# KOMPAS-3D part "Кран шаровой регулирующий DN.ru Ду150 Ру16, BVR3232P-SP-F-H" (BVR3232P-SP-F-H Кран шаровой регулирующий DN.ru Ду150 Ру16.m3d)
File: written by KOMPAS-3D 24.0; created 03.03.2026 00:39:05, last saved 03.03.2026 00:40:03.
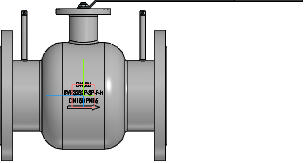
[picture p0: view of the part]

Document properties: Автор: Максим; Полное имя файла: BVR3232P-SP-F-H - Кран шаровой регулирующий DN.ru  Ду150 Ру16.cdw

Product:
- Body: Тело 1  | qty 1
    Масса: 60.240994
- Part/product: Кран шаровой регулирующий DN.ru Ду150 Ру16  | designation BVR3232P-SP-F-H
    Масса: 36.1
    Раздел спецификации: Прочие изделия
    Форматы листов документа: A2
    Примечание: D160-69427

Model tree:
1. Операция без истории:1

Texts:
  BVR3232P-SP-F-H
